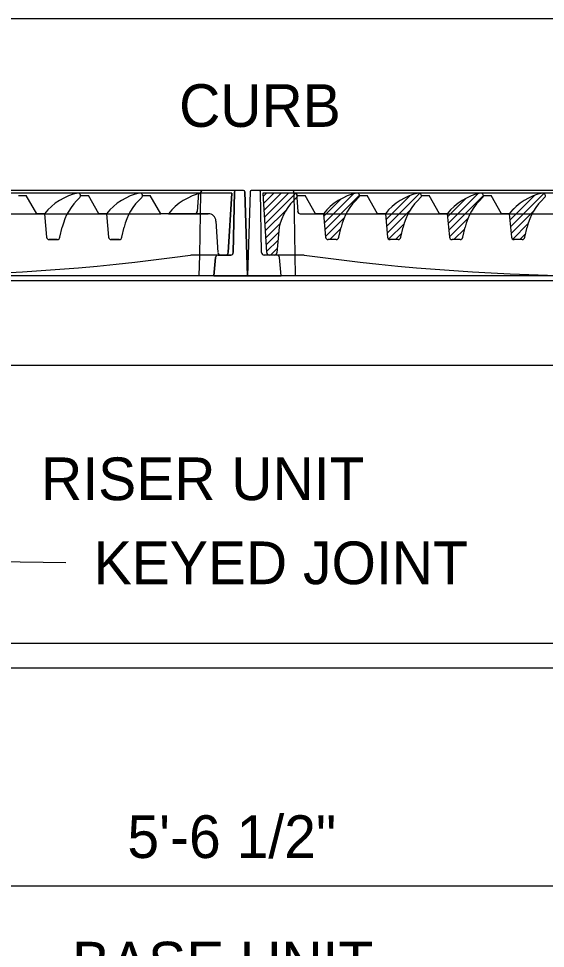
# Model space of a CAD drawing. Extents: x 9.6 to 16.8, y 2.2 to 12.2.
# Drawn here: x 11.945 to 12.686, y 7.637 to 8.944 of the extents above; entities that cross this region are included whole.
import ezdxf

# ---------------------------------------------------------------- set-up
doc = ezdxf.new("R2010")
doc.units = 0
for name, color, linetype in [('DETL-DIMS', 7, 'Continuous'), ('DETL-LINE', 7, 'Continuous'), ('DETL-NOTE', 7, 'Continuous')]:
    doc.layers.add(name, color=color, linetype=linetype)

msp = doc.modelspace()

# ---------------------------------------------------------------- linework, layer by layer
at = {"layer": 'DETL-DIMS'}
for p, q in [((12.0115, 8.1793), (11.8408, 8.182)), ((11.3073, 7.7253), (13.2464, 7.7253))]:
    msp.add_line(p, q, dxfattribs=at)
at = {"layer": 'DETL-LINE'}
for p, q in [((11.1096, 8.9441), (13.4172, 8.9441)), ((12.2615, 8.7025), (11.2703, 8.7025)), ((12.2615, 8.7025), (12.2506, 8.7025)), ((13.2636, 8.7025), (12.2723, 8.7025)), ((12.2833, 8.7025), (12.2723, 8.7025)), ((12.198, 8.6989), (12.1964, 8.6732)), ((12.1998, 8.6118), (12.2015, 8.6986)), ((12.2015, 8.6989), (12.2015, 8.7007)), ((12.2451, 8.6989), (12.2029, 8.6989)), ((12.2399, 8.6152), (12.2451, 8.6989)), ((12.247, 8.6153), (12.2488, 8.7007)), ((12.2488, 8.7007), (12.247, 8.6153)), ((12.2633, 8.7008), (12.2669, 8.5827)), ((12.2705, 8.7008), (12.2669, 8.5827)), ((12.2868, 8.6153), (12.2851, 8.7007)), ((12.2868, 8.6153), (12.2851, 8.7007)), ((12.289, 8.694), (12.2939, 8.6989)), ((12.2896, 8.6843), (12.3042, 8.6989)), ((12.2902, 8.6747), (12.3144, 8.6989)), ((12.2908, 8.665), (12.3247, 8.6989)), ((12.2914, 8.6553), (12.3347, 8.6987)), ((12.3324, 8.6989), (12.3323, 8.7007)), ((12.3341, 8.6118), (12.3324, 8.6989)), ((12.3359, 8.6989), (12.3375, 8.6732)), ((12.374, 8.666), (12.3988, 8.6908)), ((12.3748, 8.6566), (12.4159, 8.6977)), ((12.3757, 8.6472), (12.4243, 8.6958)), ((12.4616, 8.6612), (12.4957, 8.6953)), ((12.4624, 8.6518), (12.5093, 8.6986)), ((12.5483, 8.6657), (12.5737, 8.6912)), ((12.5491, 8.6563), (12.5906, 8.6978)), ((12.55, 8.6469), (12.5986, 8.6955)), ((12.6358, 8.6609), (12.6704, 8.6955)), ((12.6367, 8.6515), (12.6837, 8.6985)), ((12.6383, 8.6736), (12.6449, 8.6802)), ((11.3391, 8.6698), (12.1449, 8.6698)), ((11.9815, 8.6698), (11.9845, 8.6368)), ((12.0687, 8.6698), (12.0717, 8.6368)), ((12.1558, 8.6698), (12.2117, 8.6698)), ((12.292, 8.6457), (12.3216, 8.6752)), ((12.3411, 8.6698), (13.1469, 8.6698)), ((12.3766, 8.6378), (12.4029, 8.6641)), ((12.4633, 8.6424), (12.4954, 8.6745)), ((12.5509, 8.6375), (12.577, 8.6636)), ((12.6376, 8.6421), (12.6693, 8.6738)), ((12.0032, 8.6369), (12.0064, 8.6509)), ((12.0903, 8.6369), (12.0936, 8.6509)), ((12.2226, 8.6596), (12.2254, 8.6152)), ((12.2926, 8.636), (12.3129, 8.6563)), ((12.4654, 8.6342), (12.4871, 8.6559)), ((12.6399, 8.6341), (12.6613, 8.6555)), ((12.2932, 8.6263), (12.3108, 8.644)), ((12.3826, 8.6335), (12.3981, 8.6491)), ((12.475, 8.6335), (12.4837, 8.6422)), ((12.5572, 8.6335), (12.5723, 8.6487)), ((12.6496, 8.6335), (12.6578, 8.6418)), ((11.9882, 8.6335), (11.9996, 8.6335)), ((12.0753, 8.6335), (12.0867, 8.6335)), ((12.2938, 8.6167), (12.3099, 8.6328)), ((12.3933, 8.634), (12.3948, 8.6355)), ((12.5685, 8.6346), (12.5686, 8.6347)), ((12.1992, 8.5827), (12.1998, 8.6118)), ((12.2256, 8.6118), (12.2434, 8.6118)), ((12.2289, 8.6118), (12.2256, 8.6118)), ((12.2289, 8.6118), (12.2363, 8.6118)), ((12.2434, 8.6118), (12.2291, 8.6118)), ((12.3083, 8.6118), (12.2905, 8.6118)), ((12.2992, 8.6118), (12.309, 8.6216)), ((12.3346, 8.5827), (12.3341, 8.6118)), ((12.2197, 8.5827), (12.222, 8.6084)), ((12.3141, 8.5827), (12.3119, 8.6084)), ((11.1096, 8.5759), (13.4172, 8.5759)), ((12.2669, 8.5827), (11.156, 8.5827)), ((13.3779, 8.5827), (12.2669, 8.5827)), ((11.1096, 8.4572), (12.3616, 8.4572)), ((12.3616, 8.4572), (13.4172, 8.4572)), ((11.254, 8.0665), (13.2724, 8.0665)), ((11.2324, 8.0317), (13.2891, 8.0317))]:
    msp.add_line(p, q, dxfattribs=at)
for points in [[(12.222, 8.6084), (12.2197, 8.5827), (12.2669, 8.5827), (12.2633, 8.7008)], [(12.2705, 8.7008), (12.2669, 8.5827), (12.3141, 8.5827), (12.3119, 8.6084)], [(12.3083, 8.6118), (12.3048, 8.6118), (12.2976, 8.6118), (12.2905, 8.6118)]]:
    msp.add_lwpolyline(points, dxfattribs=at)
for centre, radius, start, end in [((12.2034, 8.7007), 0.00182, 90, 178.8778), ((12.2506, 8.7007), 0.00182, 90, 178.8542), ((12.2506, 8.7007), 0.00182, 90, 178.8542), ((12.2615, 8.7007), 0.00182, 1.7855, 90), ((12.2615, 8.7007), 0.00182, 1.7855, 90), ((12.2723, 8.7007), 0.00182, 90, 178.2145), ((12.2723, 8.7007), 0.00182, 90, 178.2145), ((12.2833, 8.7007), 0.00182, 1.1458, 90), ((12.2833, 8.7007), 0.00182, 1.1458, 90), ((12.3305, 8.7007), 0.00182, 1.1222, 90), ((12.0451, 8.6195), 0.0811, 101.6847, 141.6027), ((12.0854, 8.6323), 0.0811, 132.0547, 166.7971), ((12.0286, 8.6953), 0.00363, 312.139, 90), ((12.1322, 8.6195), 0.0811, 101.6847, 141.6027), ((12.1725, 8.6323), 0.0811, 132.0547, 166.7971), ((12.1158, 8.6953), 0.00363, 312.139, 90), ((12.2193, 8.6195), 0.0811, 101.6847, 141.6027), ((12.1928, 8.6735), 0.00363, 269.9993, 356.4126), ((12.2117, 8.659), 0.0109, 3.5763, 89.9993), ((12.3411, 8.6735), 0.00363, 183.5874, 270.0007), ((11.9882, 8.6372), 0.00363, 186.5049, 270), ((11.9996, 8.6372), 0.00363, 270, 356.0265), ((12.0753, 8.6372), 0.00363, 186.5049, 270), ((12.0867, 8.6372), 0.00363, 270, 356.0265), ((12.2256, 8.6081), 0.00363, 90, 175), ((12.2256, 8.6081), 0.00363, 90, 175), ((12.229, 8.6154), 0.00363, 183.5763, 268.8729), ((12.229, 8.6154), 0.00363, 268.8729, 271.1271), ((12.2363, 8.6154), 0.00363, 270, 356.4126), ((12.2434, 8.6154), 0.00363, 270, 358.8542), ((12.2434, 8.6154), 0.00363, 270, 358.8542), ((12.2905, 8.6154), 0.00363, 181.1458, 270), ((12.2905, 8.6154), 0.00363, 181.1458, 270), ((12.3083, 8.6081), 0.00363, 5, 90), ((12.3083, 8.6081), 0.00363, 5, 90)]:
    msp.add_arc(centre, radius, start, end, dxfattribs=at)
at = {"layer": 'DETL-NOTE'}
for p, q in [((12.2488, 8.7025), (12.2488, 8.7025)), ((12.2706, 8.7025), (12.2706, 8.7025)), ((12.2851, 8.7025), (12.2851, 8.7025)), ((12.2451, 8.6989), (11.2867, 8.6989)), ((11.9451, 8.6953), (11.956, 8.6953)), ((11.9706, 8.6698), (11.956, 8.6953)), ((12.0323, 8.6953), (12.0432, 8.6953)), ((12.0578, 8.6698), (12.0432, 8.6953)), ((12.1194, 8.6953), (12.1303, 8.6953)), ((12.1449, 8.6698), (12.1303, 8.6953)), ((12.2451, 8.6989), (12.2399, 8.6152)), ((12.2451, 8.6989), (12.2451, 8.6989)), ((13.2472, 8.6989), (12.2887, 8.6989)), ((12.2887, 8.6989), (12.2939, 8.6152)), ((12.3372, 8.6953), (12.3481, 8.6953)), ((12.3627, 8.6698), (12.3481, 8.6953)), ((12.4244, 8.6953), (12.4353, 8.6953)), ((12.4499, 8.6698), (12.4353, 8.6953)), ((12.5115, 8.6953), (12.5224, 8.6953)), ((12.537, 8.6698), (12.5224, 8.6953)), ((12.5987, 8.6953), (12.6095, 8.6953)), ((12.6241, 8.6698), (12.6095, 8.6953)), ((11.9815, 8.6698), (11.9706, 8.6698)), ((11.9815, 8.6698), (11.9845, 8.6369)), ((12.0687, 8.6698), (12.0578, 8.6698)), ((12.0687, 8.6698), (12.0717, 8.6369)), ((12.1558, 8.6698), (12.1449, 8.6698)), ((12.2117, 8.6698), (12.1558, 8.6698)), ((12.3736, 8.6698), (12.3627, 8.6698)), ((12.3736, 8.6698), (12.3766, 8.6369)), ((12.4608, 8.6698), (12.4499, 8.6698)), ((12.4608, 8.6698), (12.4638, 8.6369)), ((12.5479, 8.6698), (12.537, 8.6698)), ((12.5479, 8.6698), (12.5509, 8.6369)), ((12.635, 8.6698), (12.6241, 8.6698)), ((12.635, 8.6698), (12.638, 8.6369)), ((12.0032, 8.6369), (12.0064, 8.6509)), ((12.0903, 8.6369), (12.0936, 8.6509)), ((12.2226, 8.6596), (12.2254, 8.6152)), ((12.3114, 8.6509), (12.3084, 8.6151)), ((12.3953, 8.6369), (12.3986, 8.6509)), ((12.4824, 8.6369), (12.4857, 8.6509)), ((12.5696, 8.6369), (12.5728, 8.6509)), ((12.6567, 8.6369), (12.66, 8.6509)), ((11.9996, 8.6335), (11.9882, 8.6335)), ((12.0867, 8.6335), (12.0753, 8.6335)), ((12.3917, 8.6335), (12.3803, 8.6335)), ((12.4788, 8.6335), (12.4674, 8.6335)), ((12.5659, 8.6335), (12.5545, 8.6335)), ((12.6531, 8.6335), (12.6417, 8.6335)), ((12.2289, 8.6118), (12.1871, 8.6118)), ((12.2363, 8.6118), (12.2289, 8.6118)), ((12.3048, 8.6118), (12.2976, 8.6118)), ((12.3468, 8.6118), (12.3048, 8.6118)), ((12.2197, 8.5827), (12.2197, 8.5827)), ((12.2669, 8.5827), (12.2669, 8.5827)), ((12.2669, 8.5827), (12.2669, 8.5827)), ((12.2669, 8.5827), (12.2669, 8.5827)), ((12.2669, 8.5827), (12.2669, 8.5827)), ((12.3141, 8.5827), (12.3141, 8.5827)), ((12.3141, 8.5827), (12.3141, 8.5827))]:
    msp.add_line(p, q, dxfattribs=at)
for centre, radius, start, end in [((12.0451, 8.6195), 0.0811, 101.6847, 141.6027), ((12.0854, 8.6323), 0.0811, 132.0547, 166.7971), ((12.0286, 8.6953), 0.00363, 312.139, 90), ((12.1322, 8.6195), 0.0811, 101.6847, 141.6027), ((12.1725, 8.6323), 0.0811, 132.0547, 166.7971), ((12.1158, 8.6953), 0.00363, 312.139, 90), ((12.2193, 8.6195), 0.0811, 101.6847, 141.6027), ((12.3904, 8.6323), 0.0811, 132.0547, 166.7971), ((12.3336, 8.6953), 0.00363, 312.139, 90), ((12.4372, 8.6195), 0.0811, 101.6847, 141.6027), ((12.4775, 8.6323), 0.0811, 132.0547, 166.7971), ((12.4208, 8.6953), 0.00363, 312.139, 90), ((12.5243, 8.6195), 0.0811, 101.6847, 141.6027), ((12.5646, 8.6323), 0.0811, 132.0547, 166.7971), ((12.5079, 8.6953), 0.00363, 312.139, 90), ((12.6114, 8.6195), 0.0811, 101.6847, 141.6027), ((12.6518, 8.6323), 0.0811, 132.0547, 166.7971), ((12.595, 8.6953), 0.00363, 312.139, 90), ((12.6986, 8.6195), 0.0811, 101.6847, 141.6027), ((12.7389, 8.6323), 0.0811, 132.0547, 166.7971), ((12.6822, 8.6953), 0.00363, 312.139, 90), ((12.2117, 8.659), 0.0109, 3.5763, 90), ((11.9882, 8.6372), 0.00363, 183.9735, 270), ((11.9996, 8.6372), 0.00363, 270, 356.0265), ((12.0753, 8.6372), 0.00363, 183.9735, 270), ((12.0867, 8.6372), 0.00363, 270, 356.0265), ((12.3803, 8.6372), 0.00363, 183.9735, 270), ((12.3917, 8.6372), 0.00363, 270, 356.0265), ((12.4674, 8.6372), 0.00363, 183.9735, 270), ((12.4788, 8.6372), 0.00363, 270, 356.0265), ((12.5545, 8.6372), 0.00363, 183.9735, 270), ((12.5659, 8.6372), 0.00363, 270, 356.0265), ((12.6417, 8.6372), 0.00363, 183.9735, 270), ((12.6531, 8.6372), 0.00363, 270, 356.0265), ((11.7659, 11.6506), 3.0679, 262.1096, 277.8904), ((12.229, 8.6154), 0.00363, 183.5763, 270), ((12.2363, 8.6154), 0.00363, 270, 356.4126), ((12.2976, 8.6154), 0.00363, 183.5616, 270), ((12.3048, 8.6154), 0.00363, 270, 355.2441), ((12.768, 11.6506), 3.0679, 262.1096, 277.8904)]:
    msp.add_arc(centre, radius, start, end, dxfattribs=at)

# ---------------------------------------------------------------- texts
for s, p in [('CURB', (12.1708, 8.7919)), ('RISER UNIT', (11.9767, 8.2674)), ('KEYED JOINT', (12.0507, 8.1493)), ('5\'-6 1/2"', (12.0981, 7.7645)), ('BASE UNIT', (12.0202, 7.5868))]:
    msp.add_text(s, height=0.06, dxfattribs=at).set_placement(p)

doc.saveas('drawing.dxf')
